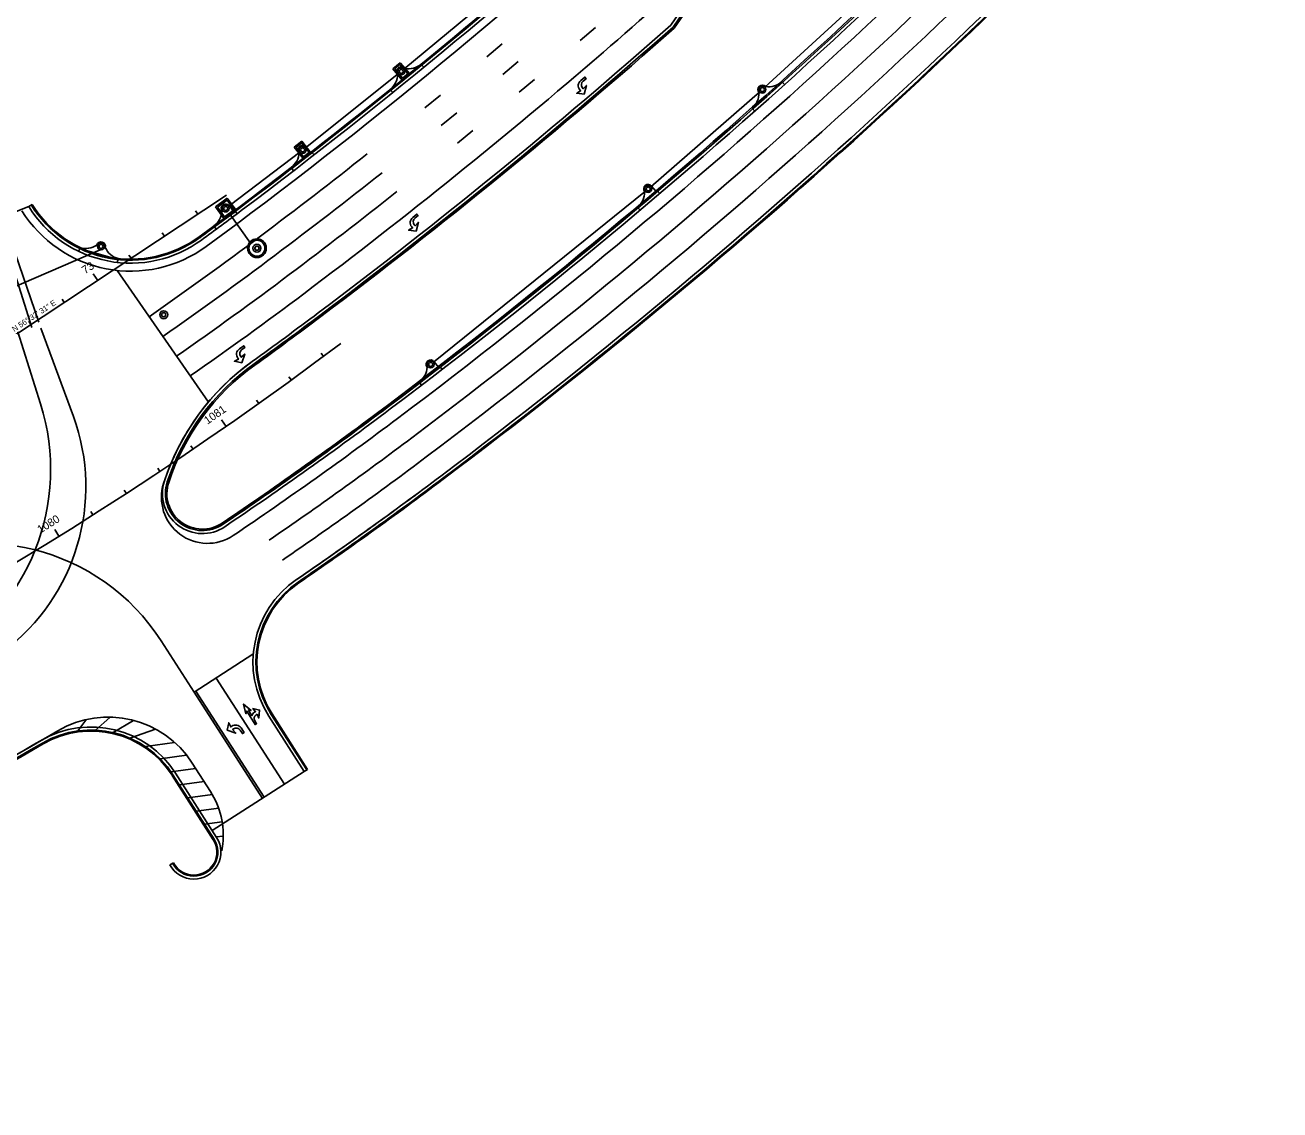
# Model space of a CAD drawing. Extents: x 468143 to 491361, y 1438528 to 1468730.
# Drawn here: x 490135 to 490762, y 1466682 to 1467224 of the extents above; entities that cross this region are included whole.
import ezdxf

# ---------------------------------------------------------------- set-up
doc = ezdxf.new("R2010")
doc.units = 0
doc.layers.add('Default', color=7, linetype='Continuous')
doc.layers.add('Xreference_dp', color=7, linetype='Continuous')

# ---------------------------------------------------------------- blocks, each defined once
blk = doc.blocks.new('POINT_DISPLAY')
at = {"layer": 'Default'}
blk.add_line((0, 0), (0, 0), dxfattribs=at)
blk = doc.blocks.new('InltCurb2_35')
at = {"layer": 'Default'}
for p, q in [((-10, 2), (-10, 0)), ((-10, 1.5), (10, 1.5)), ((10, 2), (10, 0))]:
    blk.add_line(p, q, dxfattribs=at)
for radius in [1.75, 1]:
    blk.add_circle((0, 5.5), radius, dxfattribs=at)
for centre, radius, start, end in [((0, 5.5), 2.25, 0, 180), ((-9.85, 12), 10, 269.14319, 319.46773), ((9.85, 12), 10, 220.53227, 270.85681)]:
    blk.add_arc(centre, radius, start, end, dxfattribs=at)
for p in [(-1.22, 6.76), (-0.66, 7.12), (0, 7.75), (0, 7.25), (0, 7.25), (0.7, 7.1), (1.26, 6.72), (-1.75, 5.5), (-1.75, 5.5), (-1.62, 4.84), (-1.6, 6.2), (-1.26, 4.28), (-0.7, 3.9), (0, 5.5), (0, 5.5), (0, 3.75), (0, 3.75), (0, 0), (0, 0), (0.66, 3.88), (1.22, 4.24), (1.6, 4.8), (1.62, 6.16), (1.75, 5.5), (1.75, 5.5)]:
    blk.add_blockref('POINT_DISPLAY', p, dxfattribs=at)
blk = doc.blocks.new('InltCurb1_35')
at = {"layer": 'Default'}
for p, q in [((-10, 2), (-10, 0)), ((-10, 1.5), (3, 1.5)), ((2.25, 2), (2.25, 5.5)), ((3, 2), (2.25, 2)), ((3, 0), (3, 2))]:
    blk.add_line(p, q, dxfattribs=at)
for radius in [1.75, 1]:
    blk.add_circle((0, 5.5), radius, dxfattribs=at)
for centre, radius, start, end in [((0, 5.5), 2.25, 0, 180), ((-9.85, 12), 10, 269.14319, 319.46773)]:
    blk.add_arc(centre, radius, start, end, dxfattribs=at)
for p in [(-1.22, 6.76), (-0.66, 7.12), (0, 7.75), (0, 7.25), (0, 7.25), (0.7, 7.1), (1.26, 6.72), (-1.75, 5.5), (-1.75, 5.5), (-1.62, 4.84), (-1.6, 6.2), (-1.26, 4.28), (-0.7, 3.9), (0, 5.5), (0, 5.5), (0, 3.75), (0, 3.75), (0, 0), (0, 0), (0.66, 3.88), (1.22, 4.24), (1.6, 4.8), (1.62, 6.16), (1.75, 5.5), (1.75, 5.5)]:
    blk.add_blockref('POINT_DISPLAY', p, dxfattribs=at)
blk = doc.blocks.new('JBottom35x60')
at = {"layer": 'Default'}
for p, q in [((2.42, 3.67), (-2.42, 3.67)), ((-2.42, 3.67), (-2.42, -3.67)), ((-1.75, -3), (-1.75, 3)), ((-1.75, 3), (1.75, 3)), ((1.75, 3), (1.75, -3)), ((2.42, -3.67), (2.42, 3.67)), ((-2.42, -3.67), (2.42, -3.67)), ((1.75, -3), (-1.75, -3))]:
    blk.add_line(p, q, dxfattribs=at)
for p in [(-1.75, 3), (-1.75, 0), (-1.75, 0), (0, 3), (0, 3), (0, 3), (0, 0), (0, 0), (0, 0), (1.75, 3), (-1.75, -3), (0, -3), (0, -3), (0, -3), (1.75, 0), (1.75, 0), (1.75, -3)]:
    blk.add_blockref('POINT_DISPLAY', p, dxfattribs=at)
blk = doc.blocks.new('MHCover2')
at = {"layer": 'Default'}
for radius in [2, 1.06, 1]:
    blk.add_circle((0, 0), radius, dxfattribs=at)
for p in [(-2, 0), (-2, 0), (-1.83, 0.81), (-1.39, 1.43), (-0.75, 1.85), (0, 2.5), (0, 2), (0, 2), (0, 0), (0, 0), (0, 0), (0.81, 1.83), (1.43, 1.39), (1.85, 0.75), (2, 0), (2, 0), (-1.85, -0.75), (-1.43, -1.39), (-0.81, -1.83), (0, -2), (0, -2), (0, -2.5), (0.75, -1.85), (1.39, -1.43), (1.83, -0.81)]:
    blk.add_blockref('POINT_DISPLAY', p, dxfattribs=at)
blk = doc.blocks.new('JBottom60x60')
at = {"layer": 'Default'}
for p, q in [((3.67, 3.67), (-3.67, 3.67)), ((-3.67, 3.67), (-3.67, -3.67)), ((-3, -3), (-3, 3)), ((-3, 3), (3, 3)), ((3, 3), (3, -3)), ((3.67, -3.67), (3.67, 3.67)), ((-3.67, -3.67), (3.67, -3.67)), ((3, -3), (-3, -3))]:
    blk.add_line(p, q, dxfattribs=at)
for p in [(-3, 3), (-3, 0), (-3, 0), (0, 3), (0, 3), (0, 3), (0, 0), (0, 0), (0, 0), (3, 3), (3, 0), (3, 0), (-3, -3), (0, -3), (0, -3), (0, -3), (3, -3)]:
    blk.add_blockref('POINT_DISPLAY', p, dxfattribs=at)
blk = doc.blocks.new('JBottom80Dia')
at = {"layer": 'Default'}
for radius in [4.67, 4, 4]:
    blk.add_circle((0, 0), radius, dxfattribs=at)
for p in [(-3.66, 1.61), (-2.79, 2.87), (-1.5, 3.71), (0, 4), (0, 4), (0, 4), (0, 0), (0, 0), (0, 0), (1.61, 3.66), (2.87, 2.79), (3.71, 1.5), (4, 0), (4, 0), (-4, 0), (-4, 0), (-3.71, -1.5), (-2.87, -2.79), (-1.61, -3.66), (0, -4), (0, -4), (0, -4), (1.5, -3.71), (2.79, -2.87), (3.66, -1.61)]:
    blk.add_blockref('POINT_DISPLAY', p, dxfattribs=at)
blk = doc.blocks.new('DALeftTurn_1')
at = {"layer": 'Default'}
for points in [[(5.67, 3.17), (2, 0.5), (4.33, 0.83), (4.33, 0.17)], [(6, 0.17), (6, 0.83), (8.25, 0.5), (5.67, 3.17)], [(2, -2.17), (0, -2.17), (0, -3.17), (2.67, -3.17)]]:
    blk.add_lwpolyline(points, dxfattribs=at)
for centre, radius in [((2, 0.17), 2.33), ((2.67, 0.17), 3.33)]:
    blk.add_arc(centre, radius, 270, 0, dxfattribs=at)
blk = doc.blocks.new('DARightThru')
at = {"layer": 'Default'}
for points in [[(5.05, 2.17), (8.83, 2.17), (7.83, 1), (13.08, 2.67), (7.83, 4.33), (8.83, 3.17), (0, 3.17), (0, 2.17), (2, 2.17)], [(4.33, -0.83), (2, -0.5), (5.67, -3.17), (8.25, -0.5), (6, -0.83), (6, -0.17)], [(4.33, -0.17), (4.33, -0.83)]]:
    blk.add_lwpolyline(points, dxfattribs=at)
for centre, radius, start, end in [((2, -0.17), 2.33, 360, 90), ((2.67, -0.17), 3.33, 0, 44.427)]:
    blk.add_arc(centre, radius, start, end, dxfattribs=at)

msp = doc.modelspace()

# ---------------------------------------------------------------- linework, layer by layer
at = {"layer": 'Xreference_dp'}
for p, q in [((490486.16, 1467266.12), (490457.36, 1467224.03)), ((490486.16, 1467266.12), (490457.36, 1467224.03)), ((490487.3, 1467265.13), (490458.49, 1467223.03)), ((490487.87, 1467264.64), (490459.06, 1467222.53)), ((490504.41, 1467192.95), (490566.83, 1467250.41)), ((490369.71, 1467239.99), (490323.94, 1467201.99)), ((490419.63, 1467222.89), (490412.07, 1467216.35)), ((490372.98, 1467214.61), (490365.32, 1467208.18)), ((490381.1, 1467205.76), (490373.44, 1467199.33)), ((490321.23, 1467199.78), (490274.68, 1467162.74)), ((490389.22, 1467196.91), (490381.56, 1467190.48)), ((490447.36, 1467143.26), (490501.81, 1467190.61)), ((490342.2, 1467189.07), (490334.45, 1467182.75)), ((490350.32, 1467180.21), (490342.57, 1467173.89)), ((490358.45, 1467171.35), (490350.7, 1467165.03)), ((490271.92, 1467160.59), (490237.29, 1467134.17)), ((490338.7, 1467055.5), (490444.69, 1467141)), ((490051.34, 1467017.44), (490235.32, 1467139.02)), ((490136.39, 1467133.34), (490066.06, 1467105.41)), ((490136.39, 1467133.34), (490138.09, 1467134.39)), ((490120.37, 1467128.1), (490138, 1467072.93)), ((490120.37, 1467128.1), (490138, 1467072.93)), ((490141.39, 1467075.55), (490123.54, 1467127.57)), ((490220.93, 1467129.51), (490219.83, 1467131.18)), ((490247.32, 1467115), (490236.66, 1467129.98)), ((490204.24, 1467118.48), (490203.14, 1467120.15)), ((490172.03, 1467111.76), (490076.72, 1467070.5)), ((490187.56, 1467107.46), (490186.45, 1467109.12)), ((490170.87, 1467096.43), (490168.67, 1467099.77)), ((490180.55, 1467101.39), (490226.23, 1467035.64)), ((490154.18, 1467085.4), (490153.08, 1467087.07)), ((490130.87, 1467070.64), (490142.34, 1467034.75)), ((490137.5, 1467074.38), (490136.4, 1467076.05)), ((490158.76, 1467028.42), (490142.39, 1467072.63)), ((490283.78, 1467058.46), (490282.58, 1467060.07)), ((490267.66, 1467046.62), (490266.48, 1467048.24)), ((490251.42, 1467034.95), (490250.26, 1467036.58)), ((490235.06, 1467023.45), (490232.77, 1467026.73)), ((490218.57, 1467012.12), (490217.45, 1467013.77)), ((490201.97, 1467000.96), (490200.87, 1467002.63)), ((490185.26, 1466989.98), (490184.17, 1466991.66)), ((490168.43, 1466979.18), (490167.36, 1466980.87)), ((490151.49, 1466968.55), (490149.38, 1466971.95)), ((490202.55, 1466916.36), (490219.11, 1466890.64)), ((490219.11, 1466890.64), (490248.47, 1466909.54)), ((490230.04, 1466897.67), (490264.23, 1466844.56)), ((490219.11, 1466890.64), (490253.3, 1466837.52)), ((490219.95, 1466891.18), (490254.14, 1466838.07)), ((490164.99, 1466876.71), (490160.92, 1466871.24)), ((490176.85, 1466877.97), (490169.81, 1466871.66)), ((490188.68, 1466876.38), (490178.58, 1466870.45)), ((490274.11, 1466850.92), (490256.36, 1466878.71)), ((490256.36, 1466878.71), (490274.12, 1466850.92)), ((490275.38, 1466851.73), (490257.62, 1466879.52)), ((490275.8, 1466852), (490258.04, 1466879.79)), ((490199.73, 1466872.07), (490186.96, 1466867.69)), ((490209.33, 1466865.39), (490194.73, 1466863.43)), ((490215.32, 1466859.06), (490202.14, 1466857.29)), ((490219.82, 1466852.53), (490207.47, 1466850.87)), ((490218.14, 1466855.2), (490227.25, 1466841.04)), ((490275.8, 1466852), (490274.12, 1466850.92)), ((490228.63, 1466816.89), (490208.08, 1466849.05)), ((490229.05, 1466817.17), (490208.5, 1466849.32)), ((490230.31, 1466817.98), (490209.76, 1466850.13)), ((490224.08, 1466845.97), (490211.71, 1466844.31)), ((490228.06, 1466821.49), (490274.12, 1466850.92)), ((490228.25, 1466839.4), (490215.9, 1466837.74)), ((490231.35, 1466832.68), (490220.1, 1466831.17)), ((490233.11, 1466825.78), (490224.3, 1466824.6)), ((490233.62, 1466818.71), (490230.14, 1466818.25)), ((490232.96, 1466811.37), (490233.36, 1466814.8)), ((490207, 1466804.32), (490208.76, 1466805.26))]:
    msp.add_line(p, q, dxfattribs=at)
for centre, radius, start, end in [((488571.3, 1469355.06), 2903.53, 306.9274, 317.95297), ((488571.3, 1469355.06), 2904.28, 306.9274, 317.95297), ((488571.3, 1469355.06), 2905.78, 306.9274, 317.95297), ((488571.3, 1469355.06), 2911.78, 306.9274, 317.95297), ((488571.3, 1469355.06), 2923.78, 306.9274, 317.95297), ((488571.3, 1469355.06), 2935.78, 306.9274, 317.95297), ((488571.3, 1469355.06), 2947.78, 306.9274, 317.95297), ((488571.3, 1469355.06), 2947.78, 306.9274, 317.95297), ((488571.3, 1469355.06), 2949.28, 306.9274, 317.95297), ((488571.3, 1469355.06), 2949.78, 306.9274, 317.95297), ((488571.3, 1469355.06), 2779.78, 306.9274, 312.53817), ((488571.3, 1469355.06), 2780.28, 306.9274, 312.53817), ((488571.3, 1469355.06), 2781.78, 306.9274, 312.53817), ((488571.3, 1469355.06), 2785.78, 306.41751, 312.53817), ((488571.3, 1469355.06), 2833.78, 310.81798, 312.35731), ((488571.3, 1469355.06), 2845.78, 306.9274, 311.51034), ((488571.3, 1469355.06), 2845.78, 306.9274, 311.51034), ((488571.3, 1469355.06), 2847.28, 306.9274, 311.51408), ((488571.3, 1469355.06), 2848.03, 306.9274, 311.51595), ((488571.3, 1469355.06), 2833.78, 306.9274, 310.81798), ((488571.3, 1469355.06), 2797.78, 306.9274, 308.30742), ((488571.3, 1469355.06), 2809.78, 306.9274, 308.30742), ((488571.3, 1469355.06), 2821.78, 306.9274, 308.30742), ((490187.33, 1467165.03), 60, 211.88285, 306.15157), ((490187.33, 1467165.03), 58.5, 211.88285, 306.15157), ((490187.33, 1467165.03), 58, 211.88285, 306.15157), ((490187.33, 1467165.03), 64, 211.88285, 306.15157), ((489145.02, 1468591.69), 1824.86, 306.15157, 306.9274), ((489145.02, 1468591.69), 1825.36, 306.15157, 306.9274), ((489145.02, 1468591.69), 1826.86, 306.15157, 306.9274), ((489145.02, 1468591.69), 1842.86, 304.79316, 306.9274), ((489145.02, 1468591.69), 1854.86, 304.79316, 306.9274), ((489145.02, 1468591.69), 1866.86, 304.79316, 306.9274), ((489145.02, 1468591.69), 1878.86, 304.79316, 306.9274), ((489145.02, 1468591.69), 1890.86, 305.68942, 306.9274), ((489145.02, 1468591.69), 1890.86, 305.68942, 306.9274), ((489145.02, 1468591.69), 1892.36, 305.68942, 306.9274), ((489145.02, 1468591.69), 1893.11, 305.68942, 306.9274), ((489145.02, 1468591.69), 1909.86, 245.36712, 306.9274), ((490318.14, 1466958.49), 120, 125.68942, 162.29734), ((490318.14, 1466958.49), 120, 125.68942, 161.69582), ((490318.14, 1466958.49), 118.5, 125.68942, 161.69582), ((490318.14, 1466958.49), 117.75, 125.68942, 161.69582), ((490037.59, 1467002.13), 109.71, 299.59501, 17.29502), ((489145.02, 1468591.69), 1948.61, 303.94471, 306.9274), ((489145.02, 1468591.69), 1949.36, 303.94471, 306.9274), ((490062.06, 1466993.34), 102.87, 306.956, 19.93849), ((489145.02, 1468591.69), 1950.86, 303.94471, 306.9274), ((489145.02, 1468591.69), 1956.86, 303.97537, 306.9274), ((489145.02, 1468591.69), 1968.86, 304.37058, 306.9274), ((489145.02, 1468591.69), 1980.86, 304.37058, 306.9274), ((490223.2, 1466989.9), 20, 161.69582, 303.94471), ((490223.2, 1466989.9), 18.5, 161.69582, 303.94471), ((490223.2, 1466989.9), 18.5, 161.69582, 303.94471), ((490223.2, 1466989.9), 17.75, 161.69582, 303.94471), ((489145.02, 1468591.69), 1992.86, 304.37058, 306.9274), ((489145.02, 1468591.69), 1992.86, 304.37675, 306.9274), ((489145.02, 1468591.69), 1994.36, 304.37675, 306.9274), ((489145.02, 1468591.69), 1994.86, 304.37675, 306.9274), ((490225.73, 1466987.99), 23, 162.29734, 303.97537), ((490113.32, 1466858.91), 106.12, 32.77467, 119.19694), ((490298.49, 1466905.63), 50, 124.37675, 212.58012), ((490298.49, 1466905.63), 50, 124.37675, 212.58012), ((490298.49, 1466905.63), 48.5, 124.37675, 212.58012), ((490298.49, 1466905.63), 48, 124.37675, 212.58012), ((490176.1, 1466828.13), 50, 32.77467, 120.31286), ((489145.02, 1468591.69), 1992.86, 294.00179, 300.31286), ((490167.63, 1466823.21), 50, 32.58012, 120.03817), ((490167.63, 1466823.21), 48.5, 32.58012, 120.03817), ((490167.63, 1466823.21), 48, 32.58012, 120.03817), ((489145.02, 1468591.69), 1992.86, 294.00179, 300.03817), ((489145.02, 1468591.69), 1994.36, 294.00179, 300.03817), ((489145.02, 1468591.69), 1994.86, 294.00179, 300.03817), ((490193.62, 1466819.38), 40, 353.4112, 32.77467), ((490218.92, 1466810.7), 13.52, 208.16161, 32.58012), ((490218.92, 1466810.7), 12.02, 208.16161, 32.58012), ((490218.92, 1466810.7), 11.52, 208.16161, 32.58012)]:
    msp.add_arc(centre, radius, start, end, dxfattribs=at)

# ---------------------------------------------------------------- block references
for name, p, rotation in [('InltCurb2_35', (490326.06, 1467196.62), 39.20893118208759), ('JBottom35x60', (490322.59, 1467200.88), 40.50903030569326), ('DALeftTurn_1', (490416.39, 1467195.57), -141.02092884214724), ('InltCurb2_35', (490506.78, 1467187.68), 41.86374369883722), ('InltCurb1_35', (490276.67, 1467157.32), 37.84041496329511), ('JBottom35x60', (490273.3, 1467161.67), 37.840414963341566), ('InltCurb1_35', (490449.59, 1467137.94), 40.29994614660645), ('InltCurb1_35', (490238.14, 1467127.96), 36.394345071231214), ('JBottom60x60', (490234.88, 1467132.39), 36.39434507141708), ('DALeftTurn_1', (490332.39, 1467127.11), -141.0209288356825), ('InltCurb2_35', (490170.99, 1467108.15), -16.13721772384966), ('JBottom80Dia', (490250.47, 1467112.53), 29.84469682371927), ('MHCover2', (490250.47, 1467112.53), 37.840414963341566), ('MHCover2', (490203.86, 1467079.27), 37.840414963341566), ('DALeftTurn_1', (490245.69, 1467061.15), -145.0835819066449), ('InltCurb1_35', (490340.65, 1467050.06), 37.41162312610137), ('DALeftTurn_1', (490241.38, 1466868.75), 123.90471575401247)]:
    msp.add_blockref(name, p, dxfattribs=dict(at, rotation=rotation))
at = {"layer": 'Xreference_dp', "xscale": 0.8999999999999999, "yscale": 0.8999999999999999, "rotation": 121.16398005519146}
msp.add_blockref('DARightThru', (490251.95, 1466875.86), dxfattribs=at)

# ---------------------------------------------------------------- texts
at = {"layer": 'Xreference_dp'}
for s, height, rotation, p in [('73', 4, 33.45803, (490164.57, 1467099.46)), ('N 56%%d 32\' 31" E', 2.8, 33.45803, (490129.18, 1467070.56)), ('1081', 4, 34.8018, (490225.73, 1467024.28)), ('1080', 4, 31.8018, (490142.22, 1466969.86))]:
    msp.add_text(s, height=height, rotation=rotation, dxfattribs=at).set_placement(p)

doc.saveas('drawing.dxf')
